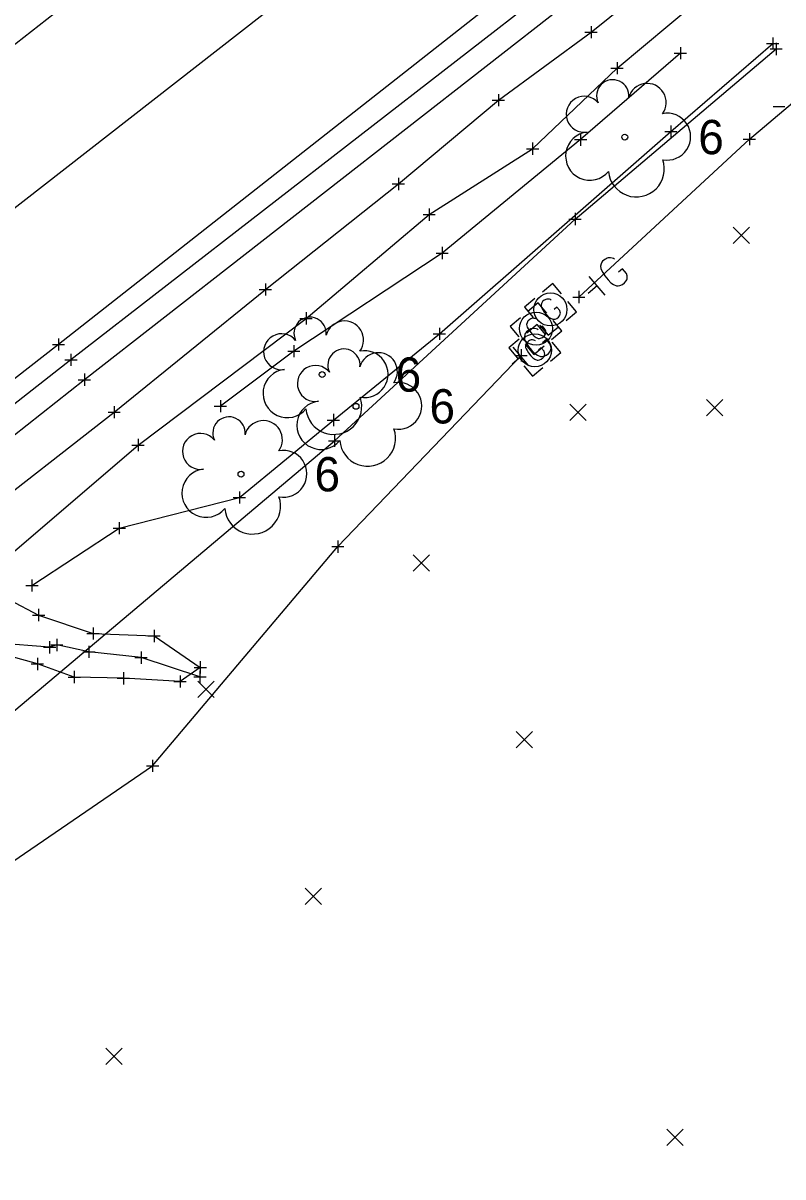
# Model space of a CAD drawing. Extents: x 2184635 to 2185378, y 369880 to 370486.
# Drawn here: x 2184907.9 to 2184969.9, y 370026.6 to 370120.8 of the extents above; entities that cross this region are included whole.
import ezdxf

# ---------------------------------------------------------------- set-up
doc = ezdxf.new("R2010")
doc.units = 0
for name, color, linetype in [('_CIVIL_CONSTRUCTION', 7, 'Continuous'), ('GE_X_Alignment', 7, 'Continuous'), ('GE_X_Alignment_100_Bearings', 7, 'Continuous'), ('GE_X_Alignment_100_Distances', 7, 'Continuous'), ('PM_X_CL_Pass_Proh_Lt', 7, 'Continuous'), ('PM_X_CL_Pass_Proh_Rt', 7, 'Continuous'), ('PM_X_Edge_Line', 7, 'Continuous'), ('PV_X_COP', 7, 'Continuous'), ('PV_X_EOP', 7, 'Continuous'), ('PV_X_Shoulder', 7, 'Continuous'), ('RD_X_Fence', 7, 'Continuous'), ('RW_X_CL', 7, 'Continuous'), ('SV_X_Break_Lines', 7, 'Continuous'), ('SV_X_Top_of_Bank', 7, 'Continuous'), ('UT_X_Gas', 7, 'Continuous'), ('VG_X_Text', 7, 'Continuous')]:
    doc.layers.add(name, color=color, linetype=linetype)

msp = doc.modelspace()

# ---------------------------------------------------------------- linework, layer by layer
at = {"layer": '_CIVIL_CONSTRUCTION'}
for p, q in [((2184965.85, 370102.804), (2184967.184, 370104.139)), ((2184965.85, 370104.139), (2184967.184, 370102.804)), ((2184952.503, 370088.368), (2184953.836, 370089.703)), ((2184952.503, 370089.703), (2184953.836, 370088.368)), ((2184963.664, 370088.74), (2184964.997, 370090.075)), ((2184963.664, 370090.075), (2184964.997, 370088.74)), ((2184939.712, 370076.043), (2184941.046, 370077.378)), ((2184939.712, 370077.378), (2184941.046, 370076.043)), ((2184922.152, 370065.732), (2184923.485, 370067.067)), ((2184922.152, 370067.067), (2184923.485, 370065.732)), ((2184948.126, 370061.612), (2184949.459, 370062.947)), ((2184948.126, 370062.947), (2184949.459, 370061.612)), ((2184930.895, 370048.818), (2184932.228, 370050.153)), ((2184930.895, 370050.153), (2184932.228, 370048.818)), ((2184914.62, 370035.743), (2184915.953, 370037.078)), ((2184914.62, 370037.078), (2184915.953, 370035.743)), ((2184960.434, 370029.125), (2184961.767, 370030.46)), ((2184960.434, 370030.46), (2184961.767, 370029.125))]:
    msp.add_line(p, q, dxfattribs=at)
at = {"layer": 'GE_X_Alignment'}
for centre in [(2184956.991, 370111.507), (2184932.289, 370092.11), (2184935.05, 370089.514), (2184925.665, 370083.969)]:
    msp.add_circle(centre, 0.24, dxfattribs=at)
for centre, radius, start, end in [((2184956.007, 370114.874), 1.317, 354.0047, 205.97412), ((2184958.817, 370114.336), 1.553, 323.82996, 165.0376), ((2184953.682, 370113.371), 1.471, 39.06254, 279.54124), ((2184960.451, 370111.543), 1.915, 259.14531, 101.45961), ((2184954.138, 370109.958), 1.974, 96.17219, 320.57371), ((2184957.938, 370108.902), 2.284, 184.94757, 19.45715), ((2184931.305, 370095.478), 1.317, 354.0047, 205.97412), ((2184934.115, 370094.939), 1.553, 323.82996, 165.0376), ((2184928.98, 370093.974), 1.471, 39.06254, 279.54124), ((2184934.066, 370092.882), 1.317, 354.0047, 205.97412), ((2184935.749, 370092.146), 1.915, 259.14531, 101.45961), ((2184936.876, 370092.343), 1.553, 323.82996, 165.0376), ((2184929.436, 370090.561), 1.974, 96.17219, 320.57371), ((2184931.74, 370091.378), 1.471, 39.06254, 279.54124), ((2184938.51, 370089.55), 1.915, 259.14531, 101.45961), ((2184932.196, 370087.966), 1.974, 96.17219, 320.57371), ((2184933.236, 370089.505), 2.284, 184.94757, 19.45715), ((2184924.681, 370087.337), 1.317, 354.0047, 205.97412), ((2184927.491, 370086.798), 1.553, 323.82996, 165.0376), ((2184935.996, 370086.909), 2.284, 184.94757, 19.45715), ((2184922.355, 370085.833), 1.471, 39.06254, 279.54124), ((2184929.125, 370084.005), 1.915, 259.14531, 101.45961), ((2184922.811, 370082.421), 1.974, 96.17219, 320.57371), ((2184926.611, 370081.364), 2.284, 184.94757, 19.45715)]:
    msp.add_arc(centre, radius, start, end, dxfattribs=at)
at = {"layer": 'GE_X_Alignment_100_Bearings'}
for p, q in [((2184970.044, 370113.98), (2184969.092, 370113.98)), ((2184955.381, 370098.589), (2184954.096, 370100.121)), ((2184954.739, 370099.355), (2184954.01, 370098.743)), ((2184950.924, 370097.427), (2184950.924, 370097.427)), ((2184949.746, 370095.86), (2184949.746, 370095.86)), ((2184949.164, 370092.816), (2184947.879, 370094.348)), ((2184948.521, 370093.582), (2184947.792, 370092.97)), ((2184949.648, 370094.096), (2184949.648, 370094.096))]:
    msp.add_line(p, q, dxfattribs=at)
for points in [[(2184956.15, 370101.526), (2184956.071, 370101.588), (2184955.963, 370101.626), (2184955.824, 370101.638), (2184955.643, 370101.64), (2184955.542, 370101.607), (2184955.469, 370101.571), (2184955.366, 370101.51), (2184955.185, 370101.359), (2184955.122, 370101.28), (2184955.09, 370101.227), (2184955.055, 370101.147), (2184955.01, 370100.955), (2184955.023, 370100.786), (2184955.079, 370100.627), (2184955.188, 370100.436), (2184955.36, 370100.17), (2184955.626, 370099.853), (2184955.856, 370099.609), (2184956.081, 370099.464), (2184956.323, 370099.359), (2184956.449, 370099.362), (2184956.59, 370099.377), (2184956.807, 370099.456), (2184956.973, 370099.595), (2184957.113, 370099.765), (2184957.148, 370099.846), (2184957.183, 370099.926), (2184957.193, 370100.037), (2184957.178, 370100.178), (2184957.124, 370100.365), (2184956.808, 370100.742), (2184956.491, 370100.476)], [(2184951.816, 370098.697), (2184951.109, 370099.54), (2184950.266, 370098.833)], [(2184949.654, 370098.319), (2184948.811, 370097.612), (2184949.518, 370096.769)], [(2184950.982, 370098.187), (2184950.925, 370098.233), (2184950.847, 370098.259), (2184950.747, 370098.268), (2184950.616, 370098.27), (2184950.544, 370098.246), (2184950.491, 370098.22), (2184950.417, 370098.176), (2184950.287, 370098.067), (2184950.242, 370098.011), (2184950.218, 370097.972), (2184950.193, 370097.914), (2184950.161, 370097.776), (2184950.17, 370097.655), (2184950.211, 370097.54), (2184950.289, 370097.403), (2184950.413, 370097.211), (2184950.604, 370096.983), (2184950.77, 370096.808), (2184950.932, 370096.703), (2184951.107, 370096.627), (2184951.197, 370096.629), (2184951.299, 370096.64), (2184951.455, 370096.697), (2184951.574, 370096.797), (2184951.675, 370096.919), (2184951.701, 370096.978), (2184951.726, 370097.036), (2184951.733, 370097.116), (2184951.722, 370097.217), (2184951.683, 370097.351), (2184951.455, 370097.623), (2184951.227, 370097.431)], [(2184952.195, 370096.535), (2184953.037, 370097.242), (2184952.33, 370098.085)], [(2184950.638, 370097.131), (2184949.931, 370097.973), (2184949.088, 370097.266)], [(2184948.475, 370096.752), (2184947.632, 370096.045), (2184948.34, 370095.202)], [(2184949.803, 370096.621), (2184949.747, 370096.666), (2184949.669, 370096.693), (2184949.569, 370096.701), (2184949.438, 370096.703), (2184949.365, 370096.679), (2184949.313, 370096.653), (2184949.239, 370096.61), (2184949.108, 370096.5), (2184949.063, 370096.444), (2184949.04, 370096.406), (2184949.015, 370096.348), (2184948.982, 370096.21), (2184948.992, 370096.088), (2184949.032, 370095.974), (2184949.111, 370095.836), (2184949.235, 370095.644), (2184949.426, 370095.416), (2184949.592, 370095.241), (2184949.754, 370095.136), (2184949.928, 370095.06), (2184950.019, 370095.063), (2184950.12, 370095.074), (2184950.276, 370095.131), (2184950.396, 370095.231), (2184950.497, 370095.353), (2184950.522, 370095.411), (2184950.547, 370095.469), (2184950.554, 370095.549), (2184950.543, 370095.651), (2184950.505, 370095.785), (2184950.277, 370096.056), (2184950.049, 370095.865)], [(2184950.54, 370095.367), (2184949.833, 370096.209), (2184948.99, 370095.502)], [(2184950.032, 370096.156), (2184950.739, 370095.314), (2184951.582, 370096.021)], [(2184951.016, 370094.968), (2184951.859, 370095.675), (2184951.152, 370096.518)], [(2184949.933, 370095.753), (2184949.854, 370095.816), (2184949.746, 370095.853), (2184949.607, 370095.866), (2184949.426, 370095.868), (2184949.325, 370095.834), (2184949.252, 370095.799), (2184949.149, 370095.738), (2184948.968, 370095.586), (2184948.905, 370095.508), (2184948.872, 370095.455), (2184948.837, 370095.374), (2184948.793, 370095.182), (2184948.806, 370095.013), (2184948.862, 370094.855), (2184948.971, 370094.664), (2184949.143, 370094.397), (2184949.409, 370094.08), (2184949.639, 370093.837), (2184949.864, 370093.691), (2184950.106, 370093.586), (2184950.232, 370093.589), (2184950.373, 370093.605), (2184950.59, 370093.684), (2184950.756, 370093.823), (2184950.896, 370093.992), (2184950.931, 370094.073), (2184950.966, 370094.154), (2184950.976, 370094.265), (2184950.96, 370094.406), (2184950.907, 370094.592), (2184950.591, 370094.969), (2184950.274, 370094.703)], [(2184948.378, 370094.988), (2184947.535, 370094.281), (2184948.242, 370093.438)], [(2184948.854, 370094.59), (2184949.561, 370093.747), (2184950.403, 370094.454)], [(2184949.706, 370094.856), (2184949.649, 370094.902), (2184949.571, 370094.929), (2184949.471, 370094.937), (2184949.341, 370094.939), (2184949.268, 370094.915), (2184949.216, 370094.889), (2184949.141, 370094.845), (2184949.011, 370094.736), (2184948.966, 370094.68), (2184948.942, 370094.642), (2184948.917, 370094.583), (2184948.885, 370094.445), (2184948.895, 370094.324), (2184948.935, 370094.21), (2184949.013, 370094.072), (2184949.137, 370093.88), (2184949.329, 370093.652), (2184949.494, 370093.477), (2184949.656, 370093.372), (2184949.831, 370093.296), (2184949.921, 370093.298), (2184950.023, 370093.31), (2184950.179, 370093.366), (2184950.298, 370093.467), (2184950.4, 370093.589), (2184950.425, 370093.647), (2184950.45, 370093.705), (2184950.457, 370093.785), (2184950.446, 370093.886), (2184950.407, 370094.021), (2184950.179, 370094.292), (2184949.951, 370094.1)], [(2184950.919, 370093.204), (2184951.761, 370093.911), (2184951.054, 370094.754)], [(2184948.756, 370092.825), (2184949.463, 370091.983), (2184950.306, 370092.69)]]:
    msp.add_lwpolyline(points, dxfattribs=at)
for centre in [(2184950.924, 370097.427), (2184949.746, 370095.86), (2184949.648, 370094.096)]:
    msp.add_circle(centre, 1.35, dxfattribs=at)
at = {"layer": 'GE_X_Alignment_100_Distances'}
msp.add_lwpolyline([(2185264.317, 370371.308), (2185225.669, 370339.838), (2185186.917, 370307.744), (2185148.745, 370277.089), (2185109.073, 370245.724), (2185070.468, 370214.753), (2185031.044, 370183.419), (2184991.951, 370153.137), (2184952.243, 370122.384), (2184912.885, 370091.687), (2184876.597, 370062.99), (2184874.528, 370062.204), (2184872.479, 370060.466), (2184871.454, 370058.823), (2184869.46, 370057.791), (2184834.83, 370028.947), (2184796.151, 369998.173), (2184773.728, 369979.618), (2184757.686, 369965.832), (2184717.275, 369935.855), (2184678.357, 369904.181)], dxfattribs=at)
at = {"layer": 'PM_X_CL_Pass_Proh_Lt'}
msp.add_lwpolyline([(2185262.142, 370374.202), (2185223.699, 370342.03), (2185185.178, 370310.659), (2185146.677, 370279.544), (2185107.738, 370248.35), (2185068.5, 370216.963), (2185029.051, 370186.04), (2184989.472, 370156.275), (2184949.89, 370125.369), (2184910.765, 370094.563), (2184870.979, 370063.529), (2184832.077, 370032.401), (2184793.204, 370001.486), (2184754.34, 369970.024), (2184715.121, 369938.505), (2184676.144, 369907.221)], dxfattribs=at)
at = {"layer": 'PM_X_CL_Pass_Proh_Rt'}
msp.add_lwpolyline([(2184772.075, 369998.33), (2184786.357, 370009.443), (2184824.962, 370040.257), (2184864.241, 370071.885), (2184905.968, 370104.805), (2184943.399, 370133.995), (2184983.483, 370165.213), (2185020.257, 370194.467), (2185061.224, 370226.635), (2185099.743, 370257.779), (2185139.182, 370289.511), (2185177.352, 370320.307), (2185216.054, 370351.804), (2185254.728, 370383.452)], dxfattribs=at)
at = {"layer": 'PM_X_Edge_Line'}
msp.add_lwpolyline([(2184661.525, 369922.948), (2184702.122, 369955.424), (2184740.459, 369986.306), (2184779.792, 370018.036), (2184818.421, 370048.832), (2184857.458, 370080.192), (2184899.139, 370112.801), (2184937.357, 370142.735), (2184976.78, 370173.64), (2185013.226, 370203.926), (2185054.743, 370235.213), (2185093.131, 370266.204), (2185132.902, 370298.208), (2185170.876, 370328.987), (2185209.713, 370360.437), (2185248.243, 370392.049)], dxfattribs=at)
at = {"layer": 'PV_X_COP'}
msp.add_lwpolyline([(2184667.936, 369914.544), (2184708.437, 369946.755), (2184746.444, 369977.522), (2184786.357, 370009.443), (2184824.962, 370040.257), (2184864.241, 370071.885), (2184905.968, 370104.805), (2184943.399, 370133.995), (2184983.483, 370165.213), (2185020.257, 370194.467), (2185061.224, 370226.635), (2185099.743, 370257.779), (2185139.182, 370289.511), (2185177.352, 370320.307), (2185216.054, 370351.804), (2185254.679, 370383.196)], dxfattribs=at)
at = {"layer": 'PV_X_EOP'}
for points in [[(2184661.562, 369922.858), (2184702.122, 369955.424), (2184740.459, 369986.306), (2184779.792, 370018.036), (2184818.421, 370048.832), (2184857.458, 370080.192), (2184899.139, 370112.801), (2184937.357, 370142.735), (2184976.78, 370173.64), (2185013.226, 370203.926), (2185054.743, 370235.213), (2185093.131, 370266.204), (2185132.902, 370298.208), (2185170.876, 370328.987), (2185209.713, 370360.437), (2185248.181, 370392.045)], [(2185262.152, 370374.256), (2185223.699, 370342.03), (2185185.178, 370310.659), (2185146.677, 370279.544), (2185107.738, 370248.35), (2185068.5, 370216.963), (2185029.051, 370186.04), (2184989.472, 370156.275), (2184949.89, 370125.369), (2184910.765, 370094.563), (2184870.979, 370063.529), (2184832.077, 370032.401), (2184793.204, 370001.486), (2184754.34, 369970.024), (2184715.121, 369938.505), (2184676.223, 369907.131)]]:
    msp.add_lwpolyline(points, dxfattribs=at)
at = {"layer": 'PV_X_Shoulder'}
msp.add_lwpolyline([(2185263.127, 370373.08), (2185224.626, 370341.08), (2185185.979, 370309.587), (2185147.251, 370278.484), (2185108.316, 370247.412), (2185069.303, 370216.141), (2185029.865, 370185.151), (2184990.36, 370154.899), (2184951.083, 370123.826), (2184911.784, 370093.315), (2184872.077, 370062.156), (2184833.336, 370030.958), (2184794.18, 369999.967), (2184755.603, 369968.652), (2184716.02, 369937.324), (2184677.487, 369905.633)], dxfattribs=at)
at = {"layer": 'RD_X_Fence'}
msp.add_lwpolyline([(2184782.754, 369936.252), (2184778.788, 369962.291), (2184805.018, 369984.824), (2184835.149, 370010.167), (2184846.096, 370019.315), (2184858.499, 370028.169), (2184882.065, 370046.135), (2184902.067, 370060.364), (2184933.298, 370086.709), (2184952.934, 370104.808), (2184969.351, 370118.703)], dxfattribs=at)
at = {"layer": 'RW_X_CL'}
for p, q in [((2184953.738, 370120.081), (2184954.738, 370120.081)), ((2184954.238, 370120.581), (2184954.238, 370119.581)), ((2184954.238, 370120.081), (2184954.238, 370120.081)), ((2184961.533, 370118.864), (2184961.533, 370117.864)), ((2184968.57, 370119.155), (2184969.57, 370119.155)), ((2184969.07, 370119.655), (2184969.07, 370118.655)), ((2184969.07, 370119.155), (2184969.07, 370119.155)), ((2184969.351, 370119.203), (2184969.351, 370118.203)), ((2184961.033, 370118.364), (2184962.033, 370118.364)), ((2184961.533, 370118.364), (2184961.533, 370118.364)), ((2184968.851, 370118.703), (2184969.851, 370118.703)), ((2184969.351, 370118.703), (2184969.351, 370118.703)), ((2184955.864, 370117.136), (2184956.864, 370117.136)), ((2184956.364, 370117.636), (2184956.364, 370116.636)), ((2184956.364, 370117.136), (2184956.364, 370117.136)), ((2184946.67, 370115.02), (2184946.67, 370114.02)), ((2184946.17, 370114.52), (2184947.17, 370114.52)), ((2184946.67, 370114.52), (2184946.67, 370114.52)), ((2184960.754, 370112.454), (2184960.754, 370111.454)), ((2184952.89, 370111.3), (2184953.89, 370111.3)), ((2184953.39, 370111.8), (2184953.39, 370110.8)), ((2184953.39, 370111.3), (2184953.39, 370111.3)), ((2184960.254, 370111.954), (2184961.254, 370111.954)), ((2184960.754, 370111.954), (2184960.754, 370111.954)), ((2184966.659, 370111.339), (2184967.659, 370111.339)), ((2184967.159, 370111.839), (2184967.159, 370110.839)), ((2184967.159, 370111.339), (2184967.159, 370111.339)), ((2184948.97, 370110.555), (2184949.97, 370110.555)), ((2184949.47, 370111.055), (2184949.47, 370110.055)), ((2184949.47, 370110.555), (2184949.47, 370110.555)), ((2184938.015, 370107.685), (2184939.015, 370107.685)), ((2184938.515, 370108.185), (2184938.515, 370107.185)), ((2184938.515, 370107.685), (2184938.515, 370107.685)), ((2184941.021, 370105.671), (2184941.021, 370104.671)), ((2184940.521, 370105.171), (2184941.521, 370105.171)), ((2184941.021, 370105.171), (2184941.021, 370105.171)), ((2184952.434, 370104.808), (2184953.434, 370104.808)), ((2184952.934, 370105.308), (2184952.934, 370104.308)), ((2184952.934, 370104.808), (2184952.934, 370104.808)), ((2184941.587, 370102.032), (2184942.587, 370102.032)), ((2184942.087, 370102.532), (2184942.087, 370101.532)), ((2184942.087, 370102.032), (2184942.087, 370102.032)), ((2184927.155, 370099.056), (2184928.155, 370099.056)), ((2184927.655, 370099.556), (2184927.655, 370098.556)), ((2184927.655, 370099.056), (2184927.655, 370099.056)), ((2184952.742, 370098.442), (2184953.742, 370098.442)), ((2184953.242, 370098.942), (2184953.242, 370097.942)), ((2184953.242, 370098.442), (2184953.242, 370098.442)), ((2184930.975, 370097.202), (2184930.975, 370096.202)), ((2184930.475, 370096.702), (2184931.475, 370096.702)), ((2184930.975, 370096.702), (2184930.975, 370096.702)), ((2184941.363, 370095.437), (2184942.363, 370095.437)), ((2184941.863, 370095.937), (2184941.863, 370094.937)), ((2184941.863, 370095.437), (2184941.863, 370095.437)), ((2184910.265, 370094.563), (2184911.265, 370094.563)), ((2184910.265, 370094.563), (2184911.265, 370094.563)), ((2184910.765, 370095.063), (2184910.765, 370094.063)), ((2184910.765, 370095.063), (2184910.765, 370094.063)), ((2184910.765, 370094.563), (2184910.765, 370094.563)), ((2184910.765, 370094.563), (2184910.765, 370094.563)), ((2184929.978, 370094.523), (2184929.978, 370093.523)), ((2184911.784, 370093.815), (2184911.784, 370092.815)), ((2184929.478, 370094.023), (2184930.478, 370094.023)), ((2184929.978, 370094.023), (2184929.978, 370094.023)), ((2184948.034, 370093.678), (2184949.034, 370093.678)), ((2184948.534, 370094.178), (2184948.534, 370093.178)), ((2184948.534, 370093.678), (2184948.534, 370093.678)), ((2184911.284, 370093.315), (2184912.284, 370093.315)), ((2184911.784, 370093.315), (2184911.784, 370093.315)), ((2184912.385, 370091.687), (2184913.385, 370091.687)), ((2184912.885, 370092.187), (2184912.885, 370091.187)), ((2184912.885, 370091.687), (2184912.885, 370091.687)), ((2184923.979, 370090.024), (2184923.979, 370089.024)), ((2184914.813, 370089.034), (2184915.813, 370089.034)), ((2184915.313, 370089.534), (2184915.313, 370088.534)), ((2184915.313, 370089.034), (2184915.313, 370089.034)), ((2184923.479, 370089.524), (2184924.479, 370089.524)), ((2184923.979, 370089.524), (2184923.979, 370089.524)), ((2184933.206, 370088.893), (2184933.206, 370087.893)), ((2184932.706, 370088.393), (2184933.706, 370088.393)), ((2184933.206, 370088.393), (2184933.206, 370088.393)), ((2184917.263, 370086.854), (2184917.263, 370085.854)), ((2184933.298, 370087.209), (2184933.298, 370086.209)), ((2184916.763, 370086.354), (2184917.763, 370086.354)), ((2184917.263, 370086.354), (2184917.263, 370086.354)), ((2184932.798, 370086.709), (2184933.798, 370086.709)), ((2184933.298, 370086.709), (2184933.298, 370086.709)), ((2184925.036, 370082.069), (2184926.036, 370082.069)), ((2184925.536, 370082.569), (2184925.536, 370081.569)), ((2184925.536, 370082.069), (2184925.536, 370082.069)), ((2184915.23, 370079.56), (2184916.23, 370079.56)), ((2184915.73, 370080.06), (2184915.73, 370079.06)), ((2184915.73, 370079.56), (2184915.73, 370079.56)), ((2184933.569, 370078.559), (2184933.569, 370077.559)), ((2184933.069, 370078.059), (2184934.069, 370078.059)), ((2184933.569, 370078.059), (2184933.569, 370078.059)), ((2184908.098, 370074.875), (2184909.098, 370074.875)), ((2184908.598, 370075.375), (2184908.598, 370074.375)), ((2184908.598, 370074.875), (2184908.598, 370074.875)), ((2184909.143, 370072.964), (2184909.143, 370071.964)), ((2184908.643, 370072.464), (2184909.643, 370072.464)), ((2184909.143, 370072.464), (2184909.143, 370072.464)), ((2184913.089, 370070.961), (2184914.089, 370070.961)), ((2184913.589, 370071.461), (2184913.589, 370070.461)), ((2184913.589, 370070.961), (2184913.589, 370070.961)), ((2184918.065, 370070.758), (2184919.065, 370070.758)), ((2184918.565, 370071.258), (2184918.565, 370070.258)), ((2184918.565, 370070.758), (2184918.565, 370070.758)), ((2184909.539, 370069.833), (2184910.539, 370069.833)), ((2184910.039, 370070.333), (2184910.039, 370069.333)), ((2184910.039, 370069.833), (2184910.039, 370069.833)), ((2184910.13, 370070.026), (2184911.13, 370070.026)), ((2184910.63, 370070.526), (2184910.63, 370069.526)), ((2184910.63, 370070.026), (2184910.63, 370070.026)), ((2184913.249, 370069.957), (2184913.249, 370068.957)), ((2184909.046, 370068.975), (2184909.046, 370067.975)), ((2184912.749, 370069.457), (2184913.749, 370069.457)), ((2184913.249, 370069.457), (2184913.249, 370069.457)), ((2184917.004, 370068.984), (2184918.004, 370068.984)), ((2184917.504, 370069.484), (2184917.504, 370068.484)), ((2184917.504, 370068.984), (2184917.504, 370068.984)), ((2184908.546, 370068.475), (2184909.546, 370068.475)), ((2184909.046, 370068.475), (2184909.046, 370068.475)), ((2184912.049, 370067.902), (2184912.049, 370066.902)), ((2184921.837, 370068.184), (2184922.837, 370068.184)), ((2184922.31, 370067.921), (2184922.31, 370066.921)), ((2184922.337, 370068.684), (2184922.337, 370067.684)), ((2184922.337, 370068.184), (2184922.337, 370068.184)), ((2184911.549, 370067.402), (2184912.549, 370067.402)), ((2184912.049, 370067.402), (2184912.049, 370067.402)), ((2184915.566, 370067.304), (2184916.566, 370067.304)), ((2184916.066, 370067.804), (2184916.066, 370066.804)), ((2184916.066, 370067.304), (2184916.066, 370067.304)), ((2184920.194, 370067.036), (2184921.194, 370067.036)), ((2184920.694, 370067.536), (2184920.694, 370066.536)), ((2184920.694, 370067.036), (2184920.694, 370067.036)), ((2184921.81, 370067.421), (2184922.81, 370067.421)), ((2184922.31, 370067.421), (2184922.31, 370067.421)), ((2184918.449, 370060.647), (2184918.449, 370059.647)), ((2184917.949, 370060.147), (2184918.949, 370060.147)), ((2184918.449, 370060.147), (2184918.449, 370060.147))]:
    msp.add_line(p, q, dxfattribs=at)
at = {"layer": 'SV_X_Break_Lines'}
for points in [[(2184877.551, 370059.028), (2184884.763, 370064.482), (2184895.426, 370072.136), (2184903.712, 370080.01), (2184915.313, 370089.034), (2184927.655, 370099.056), (2184938.515, 370107.685), (2184946.67, 370114.52), (2184954.238, 370120.081), (2184966.175, 370129.687), (2184977.964, 370136.606), (2184983.894, 370140.174), (2184990.927, 370144.207), (2185001.713, 370152.525), (2185005.564, 370154.266)], [(2184881.037, 370056.635), (2184887.302, 370061.16), (2184897.496, 370068.719), (2184906.263, 370076.899), (2184917.263, 370086.354), (2184930.975, 370096.702), (2184941.021, 370105.171), (2184949.47, 370110.555), (2184956.364, 370117.136), (2184969.257, 370127.938), (2184979.06, 370134.464), (2184985.468, 370138.655), (2184992.006, 370142.746), (2185002.661, 370150.56), (2185005.414, 370152.872)], [(2184961.533, 370118.364), (2184953.39, 370111.3), (2184942.087, 370102.032), (2184929.978, 370094.023), (2184923.979, 370089.524)], [(2184906.753, 370073.714), (2184909.143, 370072.464), (2184913.589, 370070.961), (2184918.565, 370070.758), (2184922.337, 370068.184), (2184920.694, 370067.036), (2184916.066, 370067.304), (2184912.049, 370067.402), (2184909.046, 370068.475), (2184904.99, 370069.603)], [(2184922.31, 370067.421), (2184917.504, 370068.984), (2184913.249, 370069.457), (2184910.63, 370070.026), (2184910.039, 370069.833), (2184905.778, 370070.158), (2184903.901, 370071.643)]]:
    msp.add_lwpolyline(points, dxfattribs=at)
at = {"layer": 'SV_X_Top_of_Bank'}
msp.add_lwpolyline([(2184908.598, 370074.875), (2184915.73, 370079.56), (2184925.536, 370082.069), (2184933.206, 370088.393), (2184941.863, 370095.437), (2184960.754, 370111.954), (2184969.07, 370119.155)], dxfattribs=at)
at = {"layer": 'UT_X_Gas'}
for points in [[(2184953.242, 370098.442), (2184967.159, 370111.339), (2184998.214, 370137.606), (2185039.424, 370172.123), (2185069.412, 370195.978), (2185086.695, 370210.093), (2185109.697, 370228.178), (2185131.189, 370247.901), (2185147.466, 370264.362), (2185212.955, 370317.623), (2185242.558, 370341.915), (2185269.196, 370362.683)], [(2184699.867, 369890.142), (2184718.364, 369905.922), (2184745.493, 369924.984), (2184756.714, 369934.518), (2184762.36, 369938.036), (2184795.231, 369963.996), (2184842.055, 370004.454), (2184886.231, 370038.937), (2184899.072, 370046.885), (2184918.449, 370060.147), (2184933.569, 370078.059), (2184948.534, 370093.678)]]:
    msp.add_lwpolyline(points, dxfattribs=at)

# ---------------------------------------------------------------- texts
at = {"layer": 'VG_X_Text'}
for p in [(2184962.991, 370110.107), (2184938.289, 370090.71), (2184941.05, 370088.114), (2184931.665, 370082.569)]:
    msp.add_text('6', height=2.8, dxfattribs=at).set_placement(p)

doc.saveas('drawing.dxf')
